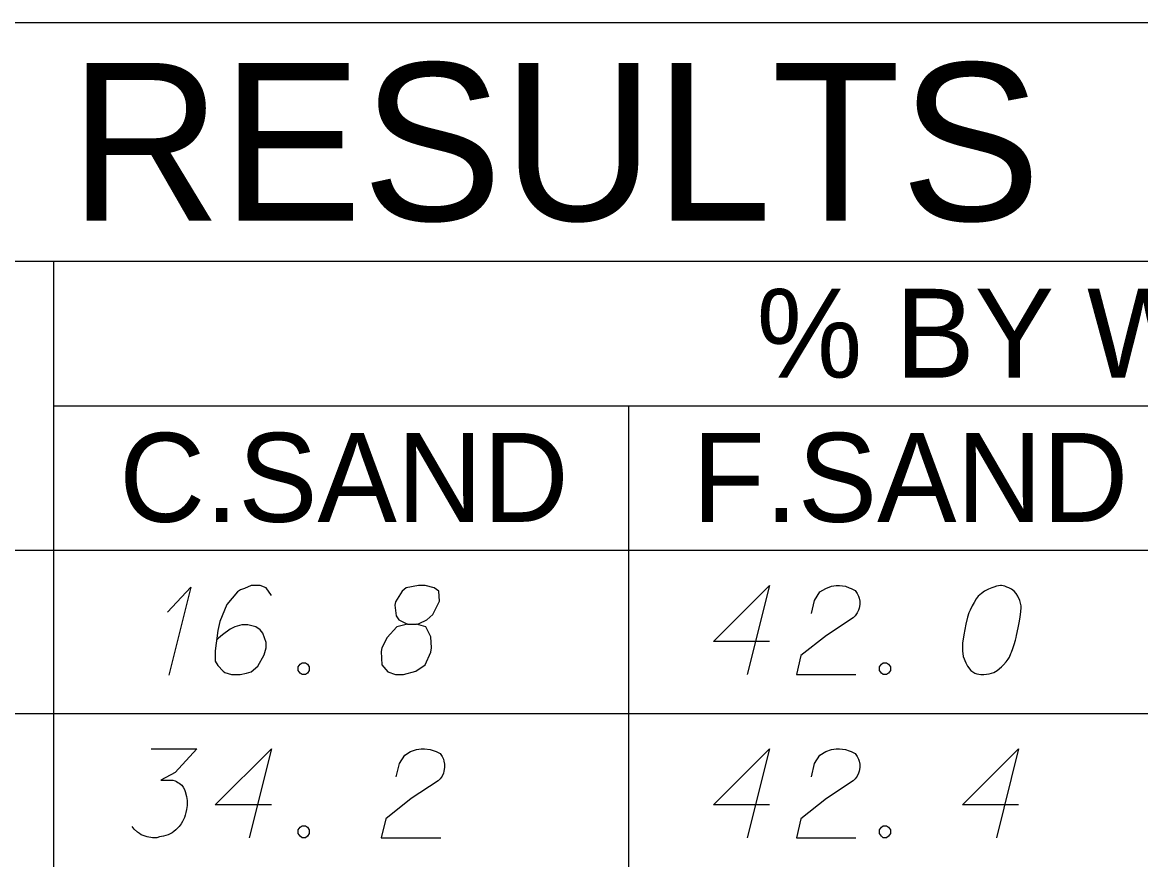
# Model space of a CAD drawing. Extents: x 2074207 to 2076812, y 516372 to 523312.
# Drawn here: x 2076524.4 to 2076584.7, y 518123.4 to 518168.6 of the extents above; entities that cross this region are included whole.
import ezdxf

# ---------------------------------------------------------------- set-up
doc = ezdxf.new("R2010")
doc.units = 0
for name, color, linetype in [('Prop DirtTable_ Soil Test Results - Outline (Major)', 7, 'Continuous'), ('Prop DirtTable_ Soil Test Results - Outline (Minor)', 7, 'Continuous'), ('Prop DirtTable_ Soil Test Results - Tx (Header - Large)', 7, 'Continuous'), ('Prop DirtTable_ Soil Test Results - Tx (Header - Small)', 7, 'Continuous'), ('Prop DirtTable_ Soil Test Results - Tx (Sample Data)', 7, 'Continuous')]:
    doc.layers.add(name, color=color, linetype=linetype)

msp = doc.modelspace()

# ---------------------------------------------------------------- linework, layer by layer
at = {"layer": 'Prop DirtTable_ Soil Test Results - Outline (Major)'}
for p, q in [((2076260.609, 518168.566), (2076811.903, 518168.566)), ((2076260.609, 518140.08), (2076811.903, 518140.08)), ((2076260.609, 518140.08), (2076811.903, 518140.08))]:
    msp.add_line(p, q, dxfattribs=at)
at = {"layer": 'Prop DirtTable_ Soil Test Results - Outline (Minor)'}
for p, q in [((2076260.609, 518155.68), (2076811.903, 518155.68)), ((2076526.074, 518155.68), (2076526.074, 518131.28)), ((2076526.074, 518147.88), (2076731.93, 518147.88)), ((2076557.094, 518147.88), (2076557.094, 518131.28)), ((2076260.609, 518131.28), (2076811.903, 518131.28)), ((2076260.609, 518131.28), (2076811.903, 518131.28)), ((2076526.074, 518131.28), (2076526.074, 518122.48)), ((2076557.094, 518131.28), (2076557.094, 518122.48))]:
    msp.add_line(p, q, dxfattribs=at)
at = {"layer": 'Prop DirtTable_ Soil Test Results - Tx (Sample Data)'}
for points in [[(2076532.22, 518136.739), (2076533.49, 518138.1), (2076532.291, 518133.337)], [(2076537.829, 518137.646), (2076537.547, 518138.062), (2076537.23, 518138.175), (2076536.736, 518138.175), (2076536.383, 518138.024), (2076536.171, 518137.948), (2076535.995, 518137.835), (2076535.431, 518137.155), (2076535.043, 518136.248), (2076534.937, 518135.756), (2076534.796, 518134.66), (2076534.796, 518134.093), (2076534.937, 518133.866), (2076535.219, 518133.564), (2076535.325, 518133.489), (2076535.678, 518133.375), (2076536.136, 518133.375), (2076536.489, 518133.451), (2076536.736, 518133.526), (2076537.089, 518133.829), (2076537.441, 518134.433), (2076537.547, 518134.811), (2076537.547, 518135.114), (2076537.371, 518135.605), (2076537.23, 518135.794), (2076536.983, 518135.945), (2076536.559, 518136.059), (2076536.242, 518136.059), (2076535.854, 518135.945), (2076535.607, 518135.832), (2076535.184, 518135.529), (2076534.972, 518135.341), (2076534.866, 518135.227)], [(2076545.167, 518136.096), (2076545.66, 518136.096), (2076545.802, 518136.134), (2076546.225, 518136.323), (2076546.542, 518136.626), (2076546.895, 518137.344), (2076546.86, 518137.873), (2076546.613, 518138.062), (2076546.119, 518138.175), (2076545.766, 518138.175), (2076545.096, 518138.062), (2076544.884, 518137.873), (2076544.532, 518137.306), (2076544.496, 518137.117), (2076544.567, 518136.55), (2076544.708, 518136.323), (2076545.167, 518136.096), (2076544.602, 518135.945), (2076544.073, 518135.378), (2076543.791, 518134.811), (2076543.756, 518134.622), (2076543.791, 518133.904), (2076544.108, 518133.526), (2076544.532, 518133.375), (2076544.955, 518133.375), (2076545.625, 518133.564), (2076546.119, 518133.904), (2076546.437, 518134.585), (2076546.472, 518134.811), (2076546.437, 518135.416), (2076546.154, 518135.945), (2076545.66, 518136.096)], [(2076564.709, 518135.152), (2076561.676, 518135.152), (2076564.709, 518138.175), (2076563.51, 518133.375)], [(2076566.967, 518136.663), (2076567.143, 518137.381), (2076567.426, 518137.835), (2076567.743, 518138.024), (2076568.06, 518138.137), (2076568.307, 518138.175), (2076568.484, 518138.175), (2076568.801, 518138.137), (2076569.013, 518138.062), (2076569.119, 518138.024), (2076569.33, 518137.911), (2076569.436, 518137.759), (2076569.507, 518137.608), (2076569.542, 518137.495), (2076569.577, 518137.344), (2076569.577, 518137.155), (2076569.542, 518136.966), (2076569.507, 518136.852), (2076569.436, 518136.701), (2076569.33, 518136.55), (2076569.225, 518136.437), (2076567.778, 518135.492), (2076566.403, 518134.396), (2076566.156, 518133.375), (2076569.366, 518133.375)], [(2076577.232, 518138.175), (2076577.162, 518138.175), (2076576.95, 518138.137), (2076576.809, 518138.1), (2076576.703, 518138.062), (2076576.527, 518137.986), (2076576.315, 518137.873), (2076576.139, 518137.759), (2076575.962, 518137.608), (2076575.856, 518137.457), (2076575.751, 518137.268), (2076575.645, 518137.079), (2076575.539, 518136.852), (2076575.468, 518136.701), (2076575.398, 518136.474), (2076575.292, 518136.096), (2076575.186, 518135.529), (2076575.116, 518135.076), (2076575.116, 518134.66), (2076575.151, 518134.358), (2076575.292, 518134.018), (2076575.398, 518133.829), (2076575.574, 518133.602), (2076575.786, 518133.451), (2076575.892, 518133.413), (2076576.103, 518133.375), (2076576.28, 518133.375), (2076576.562, 518133.413), (2076576.809, 518133.489), (2076576.985, 518133.602), (2076577.232, 518133.791), (2076577.338, 518133.904), (2076577.479, 518134.055), (2076577.585, 518134.207), (2076577.655, 518134.32), (2076577.726, 518134.509), (2076577.761, 518134.585), (2076577.832, 518134.774), (2076577.902, 518135), (2076577.973, 518135.227), (2076578.008, 518135.378), (2076578.043, 518135.492), (2076578.079, 518135.643), (2076578.149, 518135.983), (2076578.185, 518136.172), (2076578.22, 518136.361), (2076578.255, 518136.626), (2076578.29, 518136.966), (2076578.29, 518137.079), (2076578.255, 518137.23), (2076578.22, 518137.381), (2076578.114, 518137.608), (2076578.008, 518137.759), (2076577.902, 518137.873), (2076577.761, 518137.986), (2076577.62, 518138.062), (2076577.514, 518138.1), (2076577.409, 518138.137), (2076577.232, 518138.175)], [(2076539.487, 518134.018), (2076539.664, 518134.018), (2076539.769, 518133.942), (2076539.875, 518133.791), (2076539.875, 518133.602), (2076539.769, 518133.451), (2076539.664, 518133.375), (2076539.487, 518133.375), (2076539.381, 518133.451), (2076539.276, 518133.602), (2076539.276, 518133.791), (2076539.381, 518133.942), (2076539.487, 518134.018)], [(2076570.847, 518134.018), (2076571.024, 518134.018), (2076571.129, 518133.942), (2076571.235, 518133.791), (2076571.235, 518133.602), (2076571.129, 518133.451), (2076571.024, 518133.375), (2076570.847, 518133.375), (2076570.741, 518133.451), (2076570.636, 518133.602), (2076570.636, 518133.791), (2076570.741, 518133.942), (2076570.847, 518134.018)], [(2076531.339, 518129.375), (2076533.808, 518129.375), (2076532.644, 518128.09), (2076531.868, 518127.674), (2076532.503, 518127.674), (2076532.644, 518127.637), (2076532.714, 518127.599), (2076532.785, 518127.561), (2076532.855, 518127.523), (2076532.997, 518127.41), (2076533.067, 518127.296), (2076533.138, 518127.183), (2076533.173, 518127.07), (2076533.243, 518126.805), (2076533.279, 518126.578), (2076533.279, 518126.465), (2076533.279, 518126.314), (2076533.243, 518126.087), (2076533.208, 518125.936), (2076533.173, 518125.785), (2076533.138, 518125.671), (2076533.102, 518125.596), (2076533.067, 518125.52), (2076533.032, 518125.444), (2076532.961, 518125.331), (2076532.855, 518125.18), (2076532.75, 518125.066), (2076532.679, 518124.991), (2076532.573, 518124.915), (2076532.467, 518124.84), (2076532.326, 518124.764), (2076532.256, 518124.726), (2076532.009, 518124.651), (2076531.797, 518124.613), (2076531.656, 518124.575), (2076531.409, 518124.575), (2076531.127, 518124.613), (2076531.021, 518124.651), (2076530.915, 518124.689), (2076530.809, 518124.726), (2076530.704, 518124.802), (2076530.598, 518124.878), (2076530.421, 518125.029), (2076530.316, 518125.18)], [(2076537.829, 518126.352), (2076534.796, 518126.352), (2076537.829, 518129.375), (2076536.63, 518124.575)], [(2076544.567, 518127.863), (2076544.743, 518128.581), (2076545.026, 518129.035), (2076545.343, 518129.224), (2076545.66, 518129.337), (2076545.907, 518129.375), (2076546.084, 518129.375), (2076546.401, 518129.337), (2076546.613, 518129.262), (2076546.719, 518129.224), (2076546.93, 518129.111), (2076547.036, 518128.959), (2076547.107, 518128.808), (2076547.142, 518128.695), (2076547.177, 518128.544), (2076547.177, 518128.355), (2076547.142, 518128.166), (2076547.107, 518128.052), (2076547.036, 518127.901), (2076546.93, 518127.75), (2076546.825, 518127.637), (2076545.378, 518126.692), (2076544.003, 518125.596), (2076543.756, 518124.575), (2076546.966, 518124.575)], [(2076564.709, 518126.352), (2076561.676, 518126.352), (2076564.709, 518129.375), (2076563.51, 518124.575)], [(2076566.967, 518127.863), (2076567.143, 518128.581), (2076567.426, 518129.035), (2076567.743, 518129.224), (2076568.06, 518129.337), (2076568.307, 518129.375), (2076568.484, 518129.375), (2076568.801, 518129.337), (2076569.013, 518129.262), (2076569.119, 518129.224), (2076569.33, 518129.111), (2076569.436, 518128.959), (2076569.507, 518128.808), (2076569.542, 518128.695), (2076569.577, 518128.544), (2076569.577, 518128.355), (2076569.542, 518128.166), (2076569.507, 518128.052), (2076569.436, 518127.901), (2076569.33, 518127.75), (2076569.225, 518127.637), (2076567.778, 518126.692), (2076566.403, 518125.596), (2076566.156, 518124.575), (2076569.366, 518124.575)], [(2076578.149, 518126.352), (2076575.116, 518126.352), (2076578.149, 518129.375), (2076576.95, 518124.575)], [(2076539.487, 518125.218), (2076539.664, 518125.218), (2076539.769, 518125.142), (2076539.875, 518124.991), (2076539.875, 518124.802), (2076539.769, 518124.651), (2076539.664, 518124.575), (2076539.487, 518124.575), (2076539.381, 518124.651), (2076539.276, 518124.802), (2076539.276, 518124.991), (2076539.381, 518125.142), (2076539.487, 518125.218)], [(2076570.847, 518125.218), (2076571.024, 518125.218), (2076571.129, 518125.142), (2076571.235, 518124.991), (2076571.235, 518124.802), (2076571.129, 518124.651), (2076571.024, 518124.575), (2076570.847, 518124.575), (2076570.741, 518124.651), (2076570.636, 518124.802), (2076570.636, 518124.991), (2076570.741, 518125.142), (2076570.847, 518125.218)]]:
    msp.add_lwpolyline(points, dxfattribs=at)

# ---------------------------------------------------------------- texts
at = {"layer": 'Prop DirtTable_ Soil Test Results - Tx (Header - Large)'}
msp.add_text('SOIL TEST RESULTS', height=8.50001, dxfattribs=at).set_placement((2076465.656, 518157.873))
at = {"layer": 'Prop DirtTable_ Soil Test Results - Tx (Header - Small)'}
for s, height, p in [('% BY WEIGHT', 4.79998, (2076564.009, 518149.391)), ('C.SAND', 4.8, (2076529.618, 518141.616)), ('F.SAND', 4.8, (2076560.529, 518141.616))]:
    msp.add_text(s, height=height, dxfattribs=at).set_placement(p)

doc.saveas('drawing.dxf')
